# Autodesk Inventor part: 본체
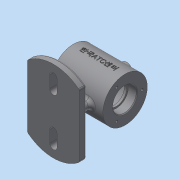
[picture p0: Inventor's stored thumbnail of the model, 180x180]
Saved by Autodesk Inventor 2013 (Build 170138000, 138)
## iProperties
Created: 2017-12
Part Number: 본체
Material: 일반
Document SubType Name: Modeling
Designer: dgall
Density: 2.71 g/cm^3
Mass: 467.692 g
Surface Area: 486.473 cm^2
Volume: 172.58 cm^3
Author: dgall
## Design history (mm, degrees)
sketch "스케치1"
  geometry: L1 (0, 0)-(70, 0); L2 (0, 0)-(0, 30); L3 (0, 30)-(70, 30); L4 (70, 30)-(70, 0)
  constraints: 8 end point, 2 perpendicular, 1 horizontal, 1 parallel
  dimensions: "d0" = 70 distance of L1.start L1.end; "d1" = 60 diameter of L3 L1
revolve "회전1" sketch "스케치1" stored, may be unused: angle "d2" = 90 deg
node "작업 평면1"
sketch "스케치2"
  geometry: L1 (70, -30)-(70, 30) reference; L2 (0, -30)-(0, 30) reference; L3 (0, 30)-(70, 30) reference; L4 (0, -30)-(70, -30) reference; L5 (0, 42.426)-(0, -42.426); L6 (70, 42.426)-(70, -42.426); A1 r 55 centre (35, 0) between (70, 42.426) and (0, 42.426); A2 r 55 centre (35, 0) between (0, -42.426) and (70, -42.426); 3 further points
  constraints: 4 end point, 4 point on circle, 2 centre point, 2 horizontal alignment, 2 midpoint, 1 collinear, 1 concentric, 1 parallel, 1 vertical alignment
  dimensions: "d6" = 70 distance between parallel lines of L6 L5; "d7" = 55 radius of A1
extrude "돌출1" join sketch "스케치2" distance "d8" = 10; taper "d9" = 0 deg
sketch "스케치3"
  geometry: L1 (0, 42.426)-(0, -42.426) reference; L2 (70, -42.426)-(70, 42.426) reference; L3 (20, 5)-(50, 5); L4 (50, -5)-(20, -5); A1 r 55 centre (35, 0) between (0, -42.426) and (70, -42.426) reference; A2 r 5 centre (20, 0) between (20, 5) and (20, -5); A3 r 5 centre (50, 0) between (50, -5) and (50, 5); 4 further points
  constraints: 4 end point, 4 point on circle, 4 vertical alignment, 2 centre point, 2 midpoint, 1 coincident, 1 equal radius, 1 horizontal alignment, 1 parallel, 1 perpendicular
  dimensions: "d13" = 30 distance of A3.centre point (20, 0); "d14" = 5 radius of A3
extrude "돌출2" join sketch "스케치3" stored distance "d15" = 10; taper "d16" = 0 deg
node "작업 평면2"
sketch "스케치4"
  geometry: C1 r 8 at (-35, 0); 1 further point
  constraints: 1 centre point, 1 horizontal alignment
  dimensions: "d18" = 16 diameter of C1; "d20" = 35 distance of point (0, 0) C1.centre
extrude "돌출3" join sketch "스케치4" stored distance "d21" = 10; taper "d22" = 0 deg
hole "구멍1" diameter "d25" = 28; stored, may be unused: countersink angle "d29" = 90 deg, drill point angle "d31" = 0 deg; dims "d23" = 10, "d24" = 10, "d26" = 6, "d27" = 32, "d28" = 12, "d30" = 15
hole "구멍2" diameter "d34" = 28; stored, may be unused: countersink angle "d38" = 90 deg, drill point angle "d40" = 0 deg; dims "d32" = 10, "d33" = 10, "d35" = 6, "d36" = 32, "d37" = 12, "d39" = 15
hole "구멍3" diameter "d43" = 50; stored, may be unused: countersink angle "d47" = 90 deg, drill point angle "d49" = 0 deg; dims "d41" = 10, "d42" = 10, "d44" = 6, "d45" = 32, "d46" = 12, "d48" = 40
hole "구멍4" diameter "d52" = 8; stored, may be unused: countersink angle "d56" = 90 deg, drill point angle "d58" = 0 deg; dims "d50" = 10, "d51" = 10, "d53" = 6, "d54" = 32, "d55" = 12, "d57" = 20
chamfer "모따기1" distance "d59" = 1; stored, may be unused: second distance "d60" = 2, angle "d61" = 45 deg
chamfer "모따기2" distance "d62" = 1; stored, may be unused: second distance "d63" = 2, angle "d64" = 45 deg
fillet "모깎기1" dims "d65" = 0.3
fillet "모깎기2" dims "d66" = 3
sketch "스케치5"
  geometry: L1 (40, 40)-(40, 24); L2 (30, 24)-(30, 40); A1 r 55 centre (35, 0) between (0, -42.426) and (70, -42.426) reference; A2 r 5 centre (50, 0) between (50, -5) and (50, 5) reference; A3 r 5 centre (35, 24) between (30, 24) and (40, 24); A4 r 5 centre (35, 40) between (40, 40) and (30, 40); 3 further points
  constraints: 4 end point, 4 point on circle, 3 horizontal alignment, 2 centre point, 2 coincident, 2 parallel, 2 vertical alignment
  dimensions: "d67" = 5 radius of A4; "d69" = 16 distance of point (35, 24) point (35, 40); "d70" = 24 vertical distance of point (35, 24) A2.centre
extrude "돌출4" cut sketch "스케치5" stored distance "d71" = 10; taper "d72" = 0 deg
node "작업 평면3"
sketch "스케치6"
  geometry: L1 (-35, 30)-(35, 30) reference; L2 (-35, -30)-(-35, 30) reference; 2 further points
  constraints: 1 other
  dimensions: "d73" = 35 distance of point (-35, 0) point (0, 0); "d74" = 30 distance from line of L1 point (0, 0)
feature "엠보싱1" sketch "스케치6" dims "d0" = 70, "d1" = 60, "d75" = 0.5, "d76" = 0
sketch "스케치7"
  geometry: C1 r 30 at (0, 0) reference; 1 further point
  constraints: 1 vertical alignment
  dimensions: "d77" = 23 distance of C1.centre point (0, 23)
hole "구멍5" sketch "스케치7" at (0, 23) diameter "d78" = 3.242; stored, may be unused: countersink angle "d82" = 90 deg, drill point angle "d84" = 118 deg; dims "d79" = 8, "d80" = 32, "d81" = 12, "d83" = 10
node "작업 평면4"
fillet "모깎기3" dims "d88" = 5
fillet "모깎기4" dims "d89" = 3
fillet "모깎기5" dims "d90" = 3
fillet "모깎기6" dims "d91" = 3
node "솔리드1"
mirror "대칭1"
pattern_circular "원형 패턴1" dims angle "d86" = 360 deg
mirror "대칭2"
node "투영된 루프1"
other parameters: "d3" = -62, "d17" = 37
